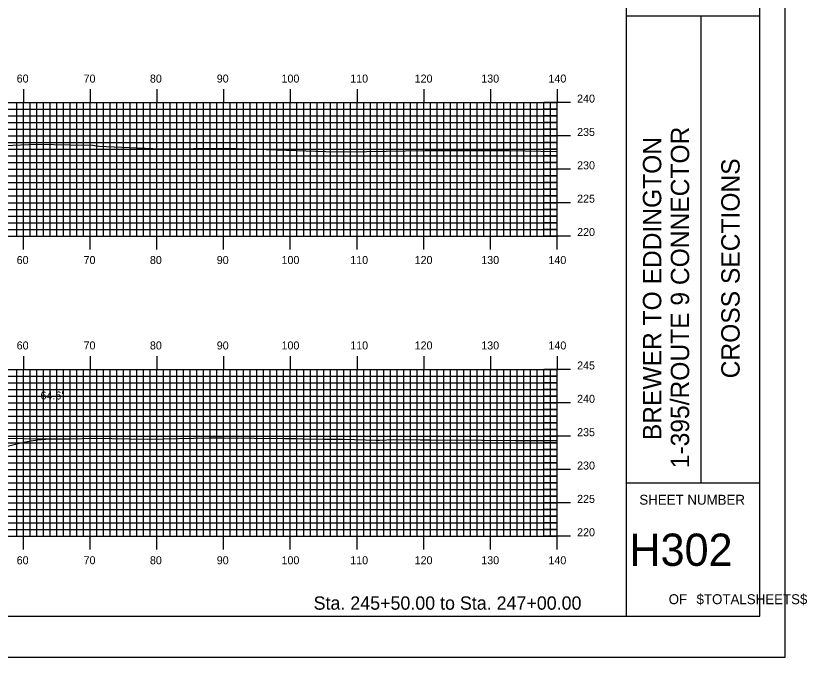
# Model space of a CAD drawing. Extents: x 1803110 to 1803453, y 442591 to 442811.
# Drawn here: x 1803334.5 to 1803453.1, y 442590.5 to 442686.7 of the extents above; entities that cross this region are included whole.
import ezdxf

# ---------------------------------------------------------------- set-up
doc = ezdxf.new("R2010")
doc.units = 0
for name, color, linetype in [('BORDER', 7, 'Continuous'), ('D_Roadway_Centerline', 7, 'Continuous'), ('D_Roadway_SlopeLines', 7, 'Continuous'), ('D_Text_Standard', 7, 'Continuous'), ('H_V ANNOTATION', 7, 'Continuous'), ('MAJOR', 7, 'Continuous'), ('MINOR', 7, 'Continuous'), ('PLOT BOUNDARY', 7, 'Continuous'), ('S_Roadway_Centerline', 7, 'Continuous')]:
    doc.layers.add(name, color=color, linetype=linetype)

msp = doc.modelspace()

# ---------------------------------------------------------------- linework, layer by layer
at = {"layer": 'BORDER'}
for p, q in [((1803426.03, 442596.67), (1803426.03, 442806.67)), ((1803426.03, 442686.67), (1803446.03, 442686.67)), ((1803437.21, 442616.67), (1803437.21, 442686.67)), ((1803426.03, 442616.67), (1803446.03, 442616.67))]:
    msp.add_line(p, q, dxfattribs=at)
msp.add_lwpolyline([(1803126.03, 442596.67), (1803446.03, 442596.67), (1803446.03, 442806.67), (1803126.03, 442806.67)], close=True, dxfattribs=at)
at = {"layer": 'D_Roadway_Centerline'}
msp.add_lwpolyline([(1803208.67, 442623.85), (1803209.92, 442623.82), (1803211.17, 442623.71), (1803212.42, 442623.52), (1803213.67, 442623.24), (1803241.45, 442616.3), (1803245.45, 442617.3), (1803255.63, 442619.84), (1803263.63, 442620.16), (1803275.63, 442620.4), (1803287.63, 442620.16), (1803295.63, 442619.84), (1803305.8, 442617.3), (1803309.8, 442616.3), (1803335.24, 442622.66), (1803336.49, 442622.93), (1803337.74, 442623.13), (1803338.99, 442623.24), (1803340.24, 442623.28)], dxfattribs=at)
at = {"layer": 'D_Roadway_SlopeLines'}
msp.add_lwpolyline([(1803309.8, 442616.3), (1803335.24, 442622.66), (1803336.49, 442622.93), (1803337.74, 442623.13), (1803338.99, 442623.24), (1803340.24, 442623.28)], dxfattribs=at)
at = {"layer": 'MAJOR'}
for p, q in [((1803335.63, 442675.67), (1803335.63, 442673.67)), ((1803345.63, 442675.67), (1803345.63, 442673.67)), ((1803355.63, 442675.67), (1803355.63, 442673.67)), ((1803365.63, 442675.67), (1803365.63, 442673.67)), ((1803375.63, 442675.67), (1803375.63, 442673.67)), ((1803385.63, 442675.67), (1803385.63, 442673.67)), ((1803395.63, 442675.67), (1803395.63, 442673.67)), ((1803405.63, 442675.67), (1803405.63, 442673.67)), ((1803415.63, 442675.67), (1803415.63, 442673.67)), ((1803135.63, 442673.67), (1803415.63, 442673.67)), ((1803135.63, 442673.67), (1803415.63, 442673.67)), ((1803335.63, 442653.67), (1803335.63, 442673.67)), ((1803345.63, 442653.67), (1803345.63, 442673.67)), ((1803355.63, 442653.67), (1803355.63, 442673.67)), ((1803365.63, 442653.67), (1803365.63, 442673.67)), ((1803375.63, 442653.67), (1803375.63, 442673.67)), ((1803385.63, 442653.67), (1803385.63, 442673.67)), ((1803395.63, 442653.67), (1803395.63, 442673.67)), ((1803405.63, 442653.67), (1803405.63, 442673.67)), ((1803417.63, 442673.67), (1803413.62, 442673.67)), ((1803415.63, 442653.67), (1803415.63, 442673.67)), ((1803415.63, 442653.67), (1803415.63, 442673.67)), ((1803135.63, 442668.67), (1803415.63, 442668.67)), ((1803417.63, 442668.67), (1803413.62, 442668.67)), ((1803135.63, 442663.67), (1803415.63, 442663.67)), ((1803417.63, 442663.67), (1803413.62, 442663.67)), ((1803135.63, 442658.67), (1803415.63, 442658.67)), ((1803417.63, 442658.67), (1803413.62, 442658.67)), ((1803135.63, 442653.67), (1803415.63, 442653.67)), ((1803135.63, 442653.67), (1803415.63, 442653.67)), ((1803335.63, 442651.66), (1803335.63, 442653.67)), ((1803345.63, 442651.66), (1803345.63, 442653.67)), ((1803355.63, 442651.66), (1803355.63, 442653.67)), ((1803365.63, 442651.66), (1803365.63, 442653.67)), ((1803375.63, 442651.66), (1803375.63, 442653.67)), ((1803385.63, 442651.66), (1803385.63, 442653.67)), ((1803395.63, 442651.66), (1803395.63, 442653.67)), ((1803405.63, 442651.66), (1803405.63, 442653.67)), ((1803417.63, 442653.67), (1803413.62, 442653.67)), ((1803415.63, 442651.66), (1803415.63, 442653.67)), ((1803335.63, 442635.67), (1803335.63, 442633.67)), ((1803345.63, 442635.67), (1803345.63, 442633.67)), ((1803355.63, 442635.67), (1803355.63, 442633.67)), ((1803365.63, 442635.67), (1803365.63, 442633.67)), ((1803375.63, 442635.67), (1803375.63, 442633.67)), ((1803385.63, 442635.67), (1803385.63, 442633.67)), ((1803395.63, 442635.67), (1803395.63, 442633.67)), ((1803405.63, 442635.67), (1803405.63, 442633.67)), ((1803415.63, 442635.67), (1803415.63, 442633.67)), ((1803135.63, 442633.67), (1803415.63, 442633.67)), ((1803135.63, 442633.67), (1803415.63, 442633.67)), ((1803335.63, 442608.67), (1803335.63, 442633.67)), ((1803345.63, 442608.67), (1803345.63, 442633.67)), ((1803355.63, 442608.67), (1803355.63, 442633.67)), ((1803365.63, 442608.67), (1803365.63, 442633.67)), ((1803375.63, 442608.67), (1803375.63, 442633.67)), ((1803385.63, 442608.67), (1803385.63, 442633.67)), ((1803395.63, 442608.67), (1803395.63, 442633.67)), ((1803405.63, 442608.67), (1803405.63, 442633.67)), ((1803417.63, 442633.67), (1803413.62, 442633.67)), ((1803415.63, 442608.67), (1803415.63, 442633.67)), ((1803415.63, 442608.67), (1803415.63, 442633.67)), ((1803135.63, 442628.67), (1803415.63, 442628.67)), ((1803417.63, 442628.67), (1803413.62, 442628.67)), ((1803135.63, 442623.67), (1803415.63, 442623.67)), ((1803417.63, 442623.67), (1803413.62, 442623.67)), ((1803135.63, 442618.67), (1803415.63, 442618.67)), ((1803417.63, 442618.67), (1803413.62, 442618.67)), ((1803135.63, 442613.67), (1803415.63, 442613.67)), ((1803417.63, 442613.67), (1803413.62, 442613.67)), ((1803135.63, 442608.67), (1803415.63, 442608.67)), ((1803135.63, 442608.67), (1803415.63, 442608.67)), ((1803335.63, 442606.66), (1803335.63, 442608.67)), ((1803345.63, 442606.66), (1803345.63, 442608.67)), ((1803355.63, 442606.66), (1803355.63, 442608.67)), ((1803365.63, 442606.66), (1803365.63, 442608.67)), ((1803375.63, 442606.66), (1803375.63, 442608.67)), ((1803385.63, 442606.66), (1803385.63, 442608.67)), ((1803395.63, 442606.66), (1803395.63, 442608.67)), ((1803405.63, 442606.66), (1803405.63, 442608.67)), ((1803417.63, 442608.67), (1803413.62, 442608.67)), ((1803415.63, 442606.66), (1803415.63, 442608.67))]:
    msp.add_line(p, q, dxfattribs=at)
at = {"layer": 'MINOR'}
for p, q in [((1803135.63, 442672.67), (1803415.63, 442672.67)), ((1803334.63, 442653.67), (1803334.63, 442673.67)), ((1803336.63, 442653.67), (1803336.63, 442673.67)), ((1803337.63, 442653.67), (1803337.63, 442673.67)), ((1803338.63, 442653.67), (1803338.63, 442673.67)), ((1803339.63, 442653.67), (1803339.63, 442673.67)), ((1803340.63, 442653.67), (1803340.63, 442673.67)), ((1803341.63, 442653.67), (1803341.63, 442673.67)), ((1803342.63, 442653.67), (1803342.63, 442673.67)), ((1803343.63, 442653.67), (1803343.63, 442673.67)), ((1803344.63, 442653.67), (1803344.63, 442673.67)), ((1803346.63, 442653.67), (1803346.63, 442673.67)), ((1803347.63, 442653.67), (1803347.63, 442673.67)), ((1803348.63, 442653.67), (1803348.63, 442673.67)), ((1803349.63, 442653.67), (1803349.63, 442673.67)), ((1803350.63, 442653.67), (1803350.63, 442673.67)), ((1803351.63, 442653.67), (1803351.63, 442673.67)), ((1803352.63, 442653.67), (1803352.63, 442673.67)), ((1803353.63, 442653.67), (1803353.63, 442673.67)), ((1803354.63, 442653.67), (1803354.63, 442673.67)), ((1803356.63, 442653.67), (1803356.63, 442673.67)), ((1803357.63, 442653.67), (1803357.63, 442673.67)), ((1803358.63, 442653.67), (1803358.63, 442673.67)), ((1803359.63, 442653.67), (1803359.63, 442673.67)), ((1803360.63, 442653.67), (1803360.63, 442673.67)), ((1803361.63, 442653.67), (1803361.63, 442673.67)), ((1803362.63, 442653.67), (1803362.63, 442673.67)), ((1803363.63, 442653.67), (1803363.63, 442673.67)), ((1803364.63, 442653.67), (1803364.63, 442673.67)), ((1803366.63, 442653.67), (1803366.63, 442673.67)), ((1803367.63, 442653.67), (1803367.63, 442673.67)), ((1803368.63, 442653.67), (1803368.63, 442673.67)), ((1803369.63, 442653.67), (1803369.63, 442673.67)), ((1803370.63, 442653.67), (1803370.63, 442673.67)), ((1803371.63, 442653.67), (1803371.63, 442673.67)), ((1803372.63, 442653.67), (1803372.63, 442673.67)), ((1803373.63, 442653.67), (1803373.63, 442673.67)), ((1803374.63, 442653.67), (1803374.63, 442673.67)), ((1803376.63, 442653.67), (1803376.63, 442673.67)), ((1803377.63, 442653.67), (1803377.63, 442673.67)), ((1803378.63, 442653.67), (1803378.63, 442673.67)), ((1803379.63, 442653.67), (1803379.63, 442673.67)), ((1803380.63, 442653.67), (1803380.63, 442673.67)), ((1803381.63, 442653.67), (1803381.63, 442673.67)), ((1803382.63, 442653.67), (1803382.63, 442673.67)), ((1803383.63, 442653.67), (1803383.63, 442673.67)), ((1803384.63, 442653.67), (1803384.63, 442673.67)), ((1803386.63, 442653.67), (1803386.63, 442673.67)), ((1803387.63, 442653.67), (1803387.63, 442673.67)), ((1803388.63, 442653.67), (1803388.63, 442673.67)), ((1803389.63, 442653.67), (1803389.63, 442673.67)), ((1803390.63, 442653.67), (1803390.63, 442673.67)), ((1803391.63, 442653.67), (1803391.63, 442673.67)), ((1803392.63, 442653.67), (1803392.63, 442673.67)), ((1803393.63, 442653.67), (1803393.63, 442673.67)), ((1803394.63, 442653.67), (1803394.63, 442673.67)), ((1803396.63, 442653.67), (1803396.63, 442673.67)), ((1803397.63, 442653.67), (1803397.63, 442673.67)), ((1803398.63, 442653.67), (1803398.63, 442673.67)), ((1803399.63, 442653.67), (1803399.63, 442673.67)), ((1803400.63, 442653.67), (1803400.63, 442673.67)), ((1803401.63, 442653.67), (1803401.63, 442673.67)), ((1803402.63, 442653.67), (1803402.63, 442673.67)), ((1803403.63, 442653.67), (1803403.63, 442673.67)), ((1803404.63, 442653.67), (1803404.63, 442673.67)), ((1803406.63, 442653.67), (1803406.63, 442673.67)), ((1803407.63, 442653.67), (1803407.63, 442673.67)), ((1803408.63, 442653.67), (1803408.63, 442673.67)), ((1803409.63, 442653.67), (1803409.63, 442673.67)), ((1803410.63, 442653.67), (1803410.63, 442673.67)), ((1803411.63, 442653.67), (1803411.63, 442673.67)), ((1803412.63, 442653.67), (1803412.63, 442673.67)), ((1803415.63, 442672.67), (1803413.62, 442672.67)), ((1803413.63, 442653.67), (1803413.63, 442673.67)), ((1803414.63, 442653.67), (1803414.63, 442673.67)), ((1803135.63, 442671.67), (1803415.63, 442671.67)), ((1803415.63, 442671.67), (1803413.62, 442671.67)), ((1803135.63, 442670.67), (1803415.63, 442670.67)), ((1803415.63, 442670.67), (1803413.62, 442670.67)), ((1803135.63, 442669.67), (1803415.63, 442669.67)), ((1803415.63, 442669.67), (1803413.62, 442669.67)), ((1803135.63, 442667.67), (1803415.63, 442667.67)), ((1803135.63, 442666.67), (1803415.63, 442666.67)), ((1803415.63, 442667.67), (1803413.62, 442667.67)), ((1803415.63, 442666.67), (1803413.62, 442666.67)), ((1803135.63, 442665.67), (1803415.63, 442665.67)), ((1803415.63, 442665.67), (1803413.62, 442665.67)), ((1803135.63, 442664.67), (1803415.63, 442664.67)), ((1803415.63, 442664.67), (1803413.62, 442664.67)), ((1803135.63, 442662.67), (1803415.63, 442662.67)), ((1803415.63, 442662.67), (1803413.62, 442662.67)), ((1803135.63, 442661.67), (1803415.63, 442661.67)), ((1803135.63, 442660.67), (1803415.63, 442660.67)), ((1803415.63, 442661.67), (1803413.62, 442661.67)), ((1803415.63, 442660.67), (1803413.62, 442660.67)), ((1803135.63, 442659.67), (1803415.63, 442659.67)), ((1803415.63, 442659.67), (1803413.62, 442659.67)), ((1803135.63, 442657.67), (1803415.63, 442657.67)), ((1803415.63, 442657.67), (1803413.62, 442657.67)), ((1803135.63, 442656.67), (1803415.63, 442656.67)), ((1803415.63, 442656.67), (1803413.62, 442656.67)), ((1803135.63, 442655.67), (1803415.63, 442655.67)), ((1803415.63, 442655.67), (1803413.62, 442655.67)), ((1803135.63, 442654.67), (1803415.63, 442654.67)), ((1803415.63, 442654.67), (1803413.62, 442654.67)), ((1803334.63, 442608.67), (1803334.63, 442633.67)), ((1803336.63, 442608.67), (1803336.63, 442633.67)), ((1803337.63, 442608.67), (1803337.63, 442633.67)), ((1803338.63, 442608.67), (1803338.63, 442633.67)), ((1803339.63, 442608.67), (1803339.63, 442633.67)), ((1803340.63, 442608.67), (1803340.63, 442633.67)), ((1803341.63, 442608.67), (1803341.63, 442633.67)), ((1803342.63, 442608.67), (1803342.63, 442633.67)), ((1803343.63, 442608.67), (1803343.63, 442633.67)), ((1803344.63, 442608.67), (1803344.63, 442633.67)), ((1803346.63, 442608.67), (1803346.63, 442633.67)), ((1803347.63, 442608.67), (1803347.63, 442633.67)), ((1803348.63, 442608.67), (1803348.63, 442633.67)), ((1803349.63, 442608.67), (1803349.63, 442633.67)), ((1803350.63, 442608.67), (1803350.63, 442633.67)), ((1803351.63, 442608.67), (1803351.63, 442633.67)), ((1803352.63, 442608.67), (1803352.63, 442633.67)), ((1803353.63, 442608.67), (1803353.63, 442633.67)), ((1803354.63, 442608.67), (1803354.63, 442633.67)), ((1803356.63, 442608.67), (1803356.63, 442633.67)), ((1803357.63, 442608.67), (1803357.63, 442633.67)), ((1803358.63, 442608.67), (1803358.63, 442633.67)), ((1803359.63, 442608.67), (1803359.63, 442633.67)), ((1803360.63, 442608.67), (1803360.63, 442633.67)), ((1803361.63, 442608.67), (1803361.63, 442633.67)), ((1803362.63, 442608.67), (1803362.63, 442633.67)), ((1803363.63, 442608.67), (1803363.63, 442633.67)), ((1803364.63, 442608.67), (1803364.63, 442633.67)), ((1803366.63, 442608.67), (1803366.63, 442633.67)), ((1803367.63, 442608.67), (1803367.63, 442633.67)), ((1803368.63, 442608.67), (1803368.63, 442633.67)), ((1803369.63, 442608.67), (1803369.63, 442633.67)), ((1803370.63, 442608.67), (1803370.63, 442633.67)), ((1803371.63, 442608.67), (1803371.63, 442633.67)), ((1803372.63, 442608.67), (1803372.63, 442633.67)), ((1803373.63, 442608.67), (1803373.63, 442633.67)), ((1803374.63, 442608.67), (1803374.63, 442633.67)), ((1803376.63, 442608.67), (1803376.63, 442633.67)), ((1803377.63, 442608.67), (1803377.63, 442633.67)), ((1803378.63, 442608.67), (1803378.63, 442633.67)), ((1803379.63, 442608.67), (1803379.63, 442633.67)), ((1803380.63, 442608.67), (1803380.63, 442633.67)), ((1803381.63, 442608.67), (1803381.63, 442633.67)), ((1803382.63, 442608.67), (1803382.63, 442633.67)), ((1803383.63, 442608.67), (1803383.63, 442633.67)), ((1803384.63, 442608.67), (1803384.63, 442633.67)), ((1803386.63, 442608.67), (1803386.63, 442633.67)), ((1803387.63, 442608.67), (1803387.63, 442633.67)), ((1803388.63, 442608.67), (1803388.63, 442633.67)), ((1803389.63, 442608.67), (1803389.63, 442633.67)), ((1803390.63, 442608.67), (1803390.63, 442633.67)), ((1803391.63, 442608.67), (1803391.63, 442633.67)), ((1803392.63, 442608.67), (1803392.63, 442633.67)), ((1803393.63, 442608.67), (1803393.63, 442633.67)), ((1803394.63, 442608.67), (1803394.63, 442633.67)), ((1803396.63, 442608.67), (1803396.63, 442633.67)), ((1803397.63, 442608.67), (1803397.63, 442633.67)), ((1803398.63, 442608.67), (1803398.63, 442633.67)), ((1803399.63, 442608.67), (1803399.63, 442633.67)), ((1803400.63, 442608.67), (1803400.63, 442633.67)), ((1803401.63, 442608.67), (1803401.63, 442633.67)), ((1803402.63, 442608.67), (1803402.63, 442633.67)), ((1803403.63, 442608.67), (1803403.63, 442633.67)), ((1803404.63, 442608.67), (1803404.63, 442633.67)), ((1803406.63, 442608.67), (1803406.63, 442633.67)), ((1803407.63, 442608.67), (1803407.63, 442633.67)), ((1803408.63, 442608.67), (1803408.63, 442633.67)), ((1803409.63, 442608.67), (1803409.63, 442633.67)), ((1803410.63, 442608.67), (1803410.63, 442633.67)), ((1803411.63, 442608.67), (1803411.63, 442633.67)), ((1803412.63, 442608.67), (1803412.63, 442633.67)), ((1803413.63, 442608.67), (1803413.63, 442633.67)), ((1803414.63, 442608.67), (1803414.63, 442633.67)), ((1803135.63, 442632.67), (1803415.63, 442632.67)), ((1803415.63, 442632.67), (1803413.62, 442632.67)), ((1803135.63, 442631.67), (1803415.63, 442631.67)), ((1803415.63, 442631.67), (1803413.62, 442631.67)), ((1803135.63, 442630.67), (1803415.63, 442630.67)), ((1803415.63, 442630.67), (1803413.62, 442630.67)), ((1803135.63, 442629.67), (1803415.63, 442629.67)), ((1803415.63, 442629.67), (1803413.62, 442629.67)), ((1803135.63, 442627.67), (1803415.63, 442627.67)), ((1803415.63, 442627.67), (1803413.62, 442627.67)), ((1803135.63, 442626.67), (1803415.63, 442626.67)), ((1803415.63, 442626.67), (1803413.62, 442626.67)), ((1803135.63, 442625.67), (1803415.63, 442625.67)), ((1803415.63, 442625.67), (1803413.62, 442625.67)), ((1803135.63, 442624.67), (1803415.63, 442624.67)), ((1803415.63, 442624.67), (1803413.62, 442624.67)), ((1803135.63, 442622.67), (1803415.63, 442622.67)), ((1803135.63, 442621.67), (1803415.63, 442621.67)), ((1803415.63, 442622.67), (1803413.62, 442622.67)), ((1803415.63, 442621.67), (1803413.62, 442621.67)), ((1803135.63, 442620.67), (1803415.63, 442620.67)), ((1803415.63, 442620.67), (1803413.62, 442620.67)), ((1803135.63, 442619.67), (1803415.63, 442619.67)), ((1803415.63, 442619.67), (1803413.62, 442619.67)), ((1803135.63, 442617.67), (1803415.63, 442617.67)), ((1803415.63, 442617.67), (1803413.62, 442617.67)), ((1803135.63, 442616.67), (1803415.63, 442616.67)), ((1803135.63, 442615.67), (1803415.63, 442615.67)), ((1803415.63, 442616.67), (1803413.62, 442616.67)), ((1803415.63, 442615.67), (1803413.62, 442615.67)), ((1803135.63, 442614.67), (1803415.63, 442614.67)), ((1803415.63, 442614.67), (1803413.62, 442614.67)), ((1803135.63, 442612.67), (1803415.63, 442612.67)), ((1803415.63, 442612.67), (1803413.62, 442612.67)), ((1803135.63, 442611.67), (1803415.63, 442611.67)), ((1803415.63, 442611.67), (1803413.62, 442611.67)), ((1803135.63, 442610.67), (1803415.63, 442610.67)), ((1803135.63, 442609.67), (1803415.63, 442609.67)), ((1803415.63, 442610.67), (1803413.62, 442610.67)), ((1803415.63, 442609.67), (1803413.62, 442609.67))]:
    msp.add_line(p, q, dxfattribs=at)
at = {"layer": 'PLOT BOUNDARY'}
msp.add_lwpolyline([(1803109.84, 442590.55), (1803449.84, 442590.55), (1803449.84, 442810.55), (1803109.84, 442810.55)], close=True, dxfattribs=at)
at = {"layer": 'S_Roadway_Centerline'}
for points in [[(1803331.57, 442667.21), (1803337.63, 442667.46), (1803342.66, 442667.36), (1803346.03, 442667.3), (1803346.92, 442667.12), (1803356.14, 442666.76), (1803366.07, 442666.84), (1803380.95, 442666.35), (1803384.32, 442666.31), (1803387.07, 442666.33), (1803395.85, 442666.49), (1803406.79, 442666.5), (1803407.7, 442666.49), (1803408.44, 442666.48), (1803415.63, 442666.36)], [(1803325.5, 442623.51), (1803338.02, 442623.28), (1803342.57, 442623.29), (1803346.24, 442623.35), (1803354.2, 442623.2), (1803363.47, 442623.42), (1803364.93, 442623.42), (1803365.69, 442623.42), (1803374.76, 442623.34), (1803376.49, 442623.3), (1803377.49, 442623.28), (1803380.56, 442623.23), (1803382.2, 442623.22), (1803383.63, 442623.2), (1803388.48, 442623.06), (1803389, 442623.05), (1803391.17, 442623.15), (1803395.12, 442623.12), (1803396.58, 442623.11), (1803404.33, 442623.05), (1803404.42, 442623.05), (1803409.38, 442623.03), (1803409.45, 442623.03), (1803409.54, 442623.03), (1803415.63, 442623.01)]]:
    msp.add_lwpolyline(points, dxfattribs=at)

# ---------------------------------------------------------------- texts
at = {"layer": 'BORDER'}
for s, p in [('1-395/ROUTE 9 CONNECTOR', (1803435.43, 442618.87)), ('BREWER TO EDDINGTON', (1803431.25, 442623.07)), ('CROSS SECTIONS', (1803443, 442632.34))]:
    msp.add_text(s, height=2.7557, rotation=90, dxfattribs=at).set_placement(p)
for s, height, p in [('SHEET NUMBER', 1.4905, (1803427.96, 442613.4)), ('H302', 4.839, (1803426.47, 442604.23)), ('OF', 1.491, (1803432.36, 442598.49)), ('$TOTALSHEETS$', 1.4905, (1803436.54, 442598.49))]:
    msp.add_text(s, height=height, dxfattribs=at).set_placement(p)
at = {"layer": 'D_Text_Standard'}
msp.add_text("64.6'", height=1.2, dxfattribs=at).set_placement((1803338.17, 442629.17))
at = {"layer": 'H_V ANNOTATION'}
for s, height, p in [('60', 1.2, (1803334.6, 442676.67)), ('70', 1.2, (1803344.63, 442676.67)), ('80', 1.2, (1803354.58, 442676.67)), ('90', 1.2, (1803364.6, 442676.67)), ('100', 1.2, (1803374.31, 442676.67)), ('110', 1.2, (1803384.61, 442676.67)), ('120', 1.2, (1803394.27, 442676.67)), ('130', 1.2, (1803404.26, 442676.67)), ('140', 1.2, (1803414.33, 442676.67)), ('240', 1.2, (1803418.63, 442673.67)), ('235', 1.2, (1803418.63, 442668.67)), ('230', 1.2, (1803418.63, 442663.67)), ('225', 1.2, (1803418.63, 442658.67)), ('220', 1.2, (1803418.63, 442653.67)), ('60', 1.2, (1803334.6, 442649.47)), ('70', 1.2, (1803344.63, 442649.47)), ('80', 1.2, (1803354.58, 442649.47)), ('90', 1.2, (1803364.6, 442649.47)), ('100', 1.2, (1803374.31, 442649.47)), ('110', 1.2, (1803384.61, 442649.47)), ('120', 1.2, (1803394.27, 442649.47)), ('130', 1.2, (1803404.26, 442649.47)), ('140', 1.2, (1803414.33, 442649.47)), ('60', 1.2, (1803334.6, 442636.67)), ('70', 1.2, (1803344.63, 442636.67)), ('80', 1.2, (1803354.58, 442636.67)), ('90', 1.2, (1803364.6, 442636.67)), ('100', 1.2, (1803374.31, 442636.67)), ('110', 1.2, (1803384.61, 442636.67)), ('120', 1.2, (1803394.27, 442636.67)), ('130', 1.2, (1803404.26, 442636.67)), ('140', 1.2, (1803414.33, 442636.67)), ('245', 1.2, (1803418.63, 442633.67)), ('240', 1.2, (1803418.63, 442628.67)), ('235', 1.2, (1803418.63, 442623.67)), ('230', 1.2, (1803418.63, 442618.67)), ('225', 1.2, (1803418.63, 442613.67)), ('220', 1.2, (1803418.63, 442608.67)), ('60', 1.2, (1803334.6, 442604.47)), ('70', 1.2, (1803344.63, 442604.47)), ('80', 1.2, (1803354.58, 442604.47)), ('90', 1.2, (1803364.6, 442604.47)), ('100', 1.2, (1803374.31, 442604.47)), ('110', 1.2, (1803384.61, 442604.47)), ('120', 1.2, (1803394.27, 442604.47)), ('130', 1.2, (1803404.26, 442604.47)), ('140', 1.2, (1803414.33, 442604.47)), ('Sta. 245+50.00 to Sta. 247+00.00', 2.0004, (1803379.12, 442597.66))]:
    msp.add_text(s, height=height, dxfattribs=at).set_placement(p)

doc.saveas('drawing.dxf')
